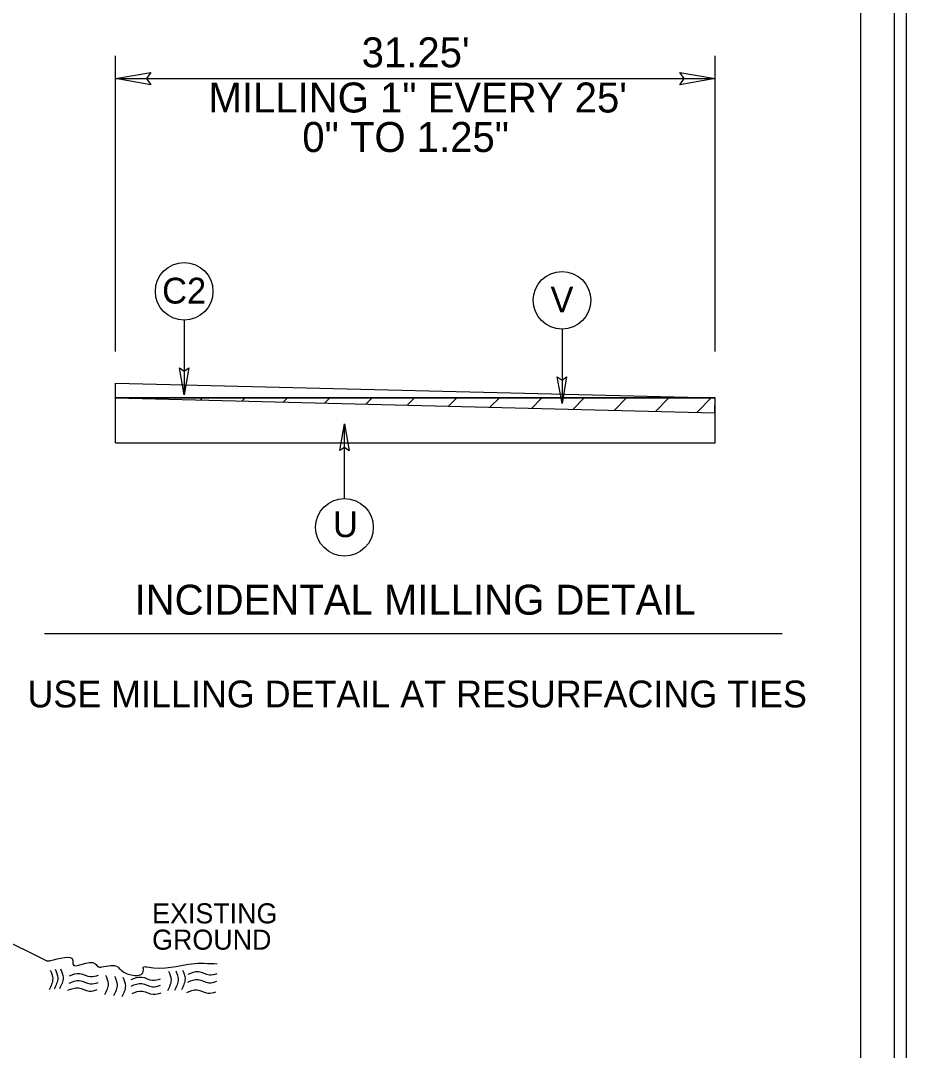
# Model space of a CAD drawing. Extents: x 575722 to 576066, y -53107 to -52774.
# Drawn here: x 575932.68 to 575965.78, y -53057.85 to -53019.37 of the extents above; entities that cross this region are included whole.
import ezdxf

# ---------------------------------------------------------------- set-up
doc = ezdxf.new("R2010")
doc.units = 0
for name, color, linetype in [('Old_Level_2', 7, 'Continuous'), ('Prop Dimension', 7, 'Continuous'), ('Prop Dimension Text', 7, 'Continuous'), ('Prop Shade Medium', 7, 'Continuous'), ('Sheet Plot Border Inside CELL', 7, 'Continuous'), ('Sheet Plot Border Outside CELL', 7, 'Continuous'), ('Sheet Typical CELL', 7, 'Continuous'), ('Typical ID Circle CELL', 7, 'Continuous'), ('Typical Pavement Slope CELL', 7, 'Continuous'), ('Typical Slope Point Local CELL', 7, 'Continuous'), ('Typical Terminator CELL', 7, 'Continuous'), ('Typical Text Grade Point CELL', 7, 'Continuous'), ('Typical Text ID Circle CELL', 7, 'Continuous'), ('Typical Text Label CELL', 7, 'Continuous')]:
    doc.layers.add(name, color=color, linetype=linetype)

msp = doc.modelspace()

# ---------------------------------------------------------------- linework, layer by layer
at = {"layer": 'Old_Level_2'}
for points in [[(575933.65, -53054.51), (575933.793, -53054.494), (575934.633, -53054.494), (575934.633, -53054.614), (575935.473, -53054.614), (575935.593, -53054.734), (575935.713, -53054.734), (575936.313, -53054.734), (575936.433, -53054.854), (575937.273, -53054.854), (575937.273, -53054.734), (575937.393, -53054.734), (575939.073, -53054.614), (575940.03, -53054.614)], [(575933.786, -53054.848), (575933.88, -53055.17), (575933.746, -53055.587)], [(575933.974, -53054.821), (575934.069, -53055.143), (575933.934, -53055.56)], [(575934.176, -53054.807), (575934.27, -53055.13), (575934.136, -53055.547)], [(575934.505, -53055.069), (575934.895, -53054.975), (575935.298, -53055.096), (575935.594, -53055.042)], [(575935.856, -53055.036), (575935.95, -53055.358), (575935.816, -53055.775)], [(575936.192, -53055.076), (575936.286, -53055.399), (575936.152, -53055.815)], [(575938.208, -53054.888), (575938.302, -53055.21), (575938.168, -53055.627)], [(575938.477, -53054.874), (575938.571, -53055.197), (575938.437, -53055.614)], [(575938.732, -53054.848), (575938.826, -53055.17), (575938.692, -53055.587)], [(575938.941, -53055.002), (575939.331, -53054.908), (575939.734, -53055.029), (575940.03, -53054.975)], [(575934.492, -53055.338), (575934.882, -53055.244), (575935.285, -53055.365), (575935.581, -53055.311)], [(575936.501, -53055.116), (575936.595, -53055.439), (575936.461, -53055.856)], [(575936.817, -53055.204), (575937.207, -53055.11), (575937.61, -53055.231), (575937.906, -53055.177)], [(575936.817, -53055.446), (575937.207, -53055.352), (575937.61, -53055.473), (575937.906, -53055.419)], [(575938.927, -53055.298), (575939.317, -53055.204), (575939.72, -53055.325), (575940.016, -53055.271)], [(575934.452, -53055.607), (575934.841, -53055.513), (575935.245, -53055.634), (575935.54, -53055.58)], [(575936.844, -53055.728), (575937.234, -53055.634), (575937.637, -53055.755), (575937.933, -53055.701)], [(575938.887, -53055.688), (575939.277, -53055.594), (575939.68, -53055.715), (575939.976, -53055.661)]]:
    msp.add_spline(points, degree=3, dxfattribs=at)
at = {"layer": 'Prop Dimension'}
for p, q in [((575936.23, -53031.734), (575936.23, -53020.692)), ((575958.63, -53031.734), (575958.63, -53020.692))]:
    msp.add_line(p, q, dxfattribs=at)
at = {"layer": 'Prop Shade Medium'}
for p, q in [((575936.23, -53021.541), (575958.63, -53021.541)), ((575936.313, -53033.476), (575936.315, -53033.474))]:
    msp.add_line(p, q, dxfattribs=at)
at = {"layer": 'Sheet Plot Border Inside CELL'}
msp.add_lwpolyline([(575965.33, -52999.112), (575798.68, -52999.112), (575798.68, -53104.622), (575965.33, -53104.622)], close=True, dxfattribs=at)
at = {"layer": 'Sheet Plot Border Outside CELL'}
msp.add_lwpolyline([(575965.78, -52996.867), (575797.38, -52996.867), (575797.38, -53106.867), (575965.78, -53106.867)], close=True, dxfattribs=at)
at = {"layer": 'Sheet Typical CELL'}
msp.add_lwpolyline([(575964.08, -52999.367), (575814.08, -52999.367), (575814.08, -53104.367), (575964.08, -53104.367)], close=True, dxfattribs=at)
at = {"layer": 'Typical ID Circle CELL'}
for p, q in [((575938.793, -53030.567), (575938.793, -53033.35)), ((575952.913, -53030.899), (575952.913, -53033.683)), ((575944.783, -53037.227), (575944.783, -53034.443))]:
    msp.add_line(p, q, dxfattribs=at)
for centre in [(575938.793, -53029.49), (575952.913, -53029.822), (575944.783, -53038.304)]:
    msp.add_circle(centre, 1.077, dxfattribs=at)
at = {"layer": 'Typical Pavement Slope CELL'}
for p, q in [((575936.23, -53032.914), (575958.63, -53033.474)), ((575936.23, -53033.474), (575936.23, -53032.914)), ((575936.23, -53033.474), (575958.63, -53033.474)), ((575936.23, -53035.154), (575936.23, -53033.474)), ((575937.858, -53033.514), (575937.899, -53033.474)), ((575939.404, -53033.553), (575939.483, -53033.474)), ((575940.949, -53033.592), (575941.067, -53033.474)), ((575942.494, -53033.63), (575942.651, -53033.474)), ((575944.039, -53033.669), (575944.235, -53033.474)), ((575945.585, -53033.708), (575945.819, -53033.474)), ((575947.13, -53033.746), (575947.403, -53033.474)), ((575948.675, -53033.785), (575948.987, -53033.474)), ((575950.221, -53033.823), (575950.57, -53033.474)), ((575951.766, -53033.862), (575952.154, -53033.474)), ((575953.311, -53033.901), (575953.738, -53033.474)), ((575954.856, -53033.939), (575955.322, -53033.474)), ((575956.402, -53033.978), (575956.906, -53033.474)), ((575957.947, -53034.017), (575958.49, -53033.474)), ((575958.63, -53035.154), (575958.63, -53033.474)), ((575936.23, -53035.154), (575958.63, -53035.154))]:
    msp.add_line(p, q, dxfattribs=at)
msp.add_lwpolyline([(575958.616, -53034.033), (575958.63, -53033.474), (575936.23, -53033.474)], close=True, dxfattribs=at)
at = {"layer": 'Typical Slope Point Local CELL'}
msp.add_line((575933.65, -53054.51), (575922.488, -53048.928), dxfattribs=at)
at = {"layer": 'Typical Terminator CELL'}
for points in [[(575937.542, -53021.767), (575936.23, -53021.541), (575937.549, -53021.307), (575937.381, -53021.541)], [(575957.317, -53021.315), (575958.63, -53021.541), (575957.31, -53021.774), (575957.478, -53021.541)], [(575938.965, -53032.353), (575938.793, -53033.35), (575938.616, -53032.347), (575938.793, -53032.475)], [(575953.085, -53032.685), (575952.913, -53033.683), (575952.736, -53032.68), (575952.913, -53032.807)], [(575944.611, -53035.441), (575944.783, -53034.443), (575944.96, -53035.446), (575944.783, -53035.319)]]:
    msp.add_lwpolyline(points, close=True, dxfattribs=at)
at = {"layer": 'Typical Text Label CELL'}
msp.add_line((575933.572, -53042.278), (575961.137, -53042.278), dxfattribs=at)

# ---------------------------------------------------------------- texts
at = {"layer": 'Prop Dimension Text'}
for s, p in [("31.25'", (575945.425, -53021.119)), ('MILLING 1" EVERY 25\'', (575939.703, -53022.806)), ('0" TO 1.25"', (575943.207, -53024.282))]:
    msp.add_text(s, height=1.12, dxfattribs=at).set_placement(p)
at = {"layer": 'Typical Text Grade Point CELL'}
for s, p in [('EXISTING', (575937.596, -53053.106)), ('GROUND', (575937.596, -53054.089))]:
    msp.add_text(s, height=0.75, dxfattribs=at).set_placement(p)
at = {"layer": 'Typical Text ID Circle CELL'}
for s, height, p in [('C2', 0.9641, (575937.969, -53029.945)), ('V', 0.964, (575952.481, -53030.277)), ('U', 0.964, (575944.355, -53038.673))]:
    msp.add_text(s, height=height, dxfattribs=at).set_placement(p)
at = {"layer": 'Typical Text Label CELL'}
msp.add_text('INCIDENTAL MILLING DETAIL', height=1.12, dxfattribs=at).set_placement((575936.938, -53041.571))
msp.add_text('USE MILLING DETAIL AT RESURFACING TIES', height=1.00259, rotation=360, dxfattribs=at).set_placement((575932.936, -53045.035))

doc.saveas('drawing.dxf')
